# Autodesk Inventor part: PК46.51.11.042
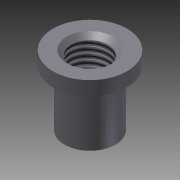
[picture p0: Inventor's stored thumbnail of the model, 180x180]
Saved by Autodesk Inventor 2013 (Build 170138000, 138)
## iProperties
Shininess: 64.0
Length Units: 11269
Angle Units: 11279
Time Units: 11290
Mass Units: 11283
Length Display Precision: 3
Angle Display Precision: 2
Compacted: True
Part Number: PК46.51.11.042
Document SubType Name: Modeling
Created: 2005-02
Material: Steel, Mild
Designer: =<Author>
Manufacturer: Standard
Standards Organization: Custom
Description: bush
Density: 7.86 g/cm^3
Mass: 7.57913 g
Surface Area: 12.0992 cm^2
Volume: 0.964266 cm^3
Density: 0.0
Volumn: 0.0
Area: 0.0
PropertySet Name: Model Information
Control State: 0
Master: False
Checked Out: False
Checked Out Date: 2008-10-15
Last Check In Date: 2008-10-15
d0: 11.000 mm
d1: 8.000 mm
d2: 12.000 mm
d3: 0.00 deg
d4: 16.000 mm
d5: 3.000 mm
d6: 0.00 deg
d9: 0.500 mm
d10: 1.000 mm
Author: PVitaliy
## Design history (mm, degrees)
sketch "Эскиз1"
  geometry: C1 r 5.5 at (0, 0); C2 r 4 at (0, 0)
  constraints: 2 centre point, 1 coincident, 1 other
  dimensions: "d0" = 11 diameter of C1; "d1" = 8 diameter of C2
extrude "Выдавливание1" new body sketch "Эскиз1" distance "d2" = 12; taper "d3" = 0 deg
sketch "Эскиз2"
  geometry: C1 r 4 at (0, 0) reference; C2 r 5.5 at (0, 0) reference; C3 r 8 at (0, 0)
  constraints: 1 centre point, 1 coincident
  dimensions: "d4" = 16 diameter of C3
extrude "Выдавливание2" join sketch "Эскиз2" distance "d5" = 3; taper "d6" = 0 deg
feature "Резьба1" dims "d7" = 10, "d8" = 0
fillet "Сопряжение1" dims "d9" = 0.5
chamfer "Фаска1" distance "d10" = 1; stored, may be unused: second distance "d11" = 2, angle "d12" = 45 deg
body "Solid1"
